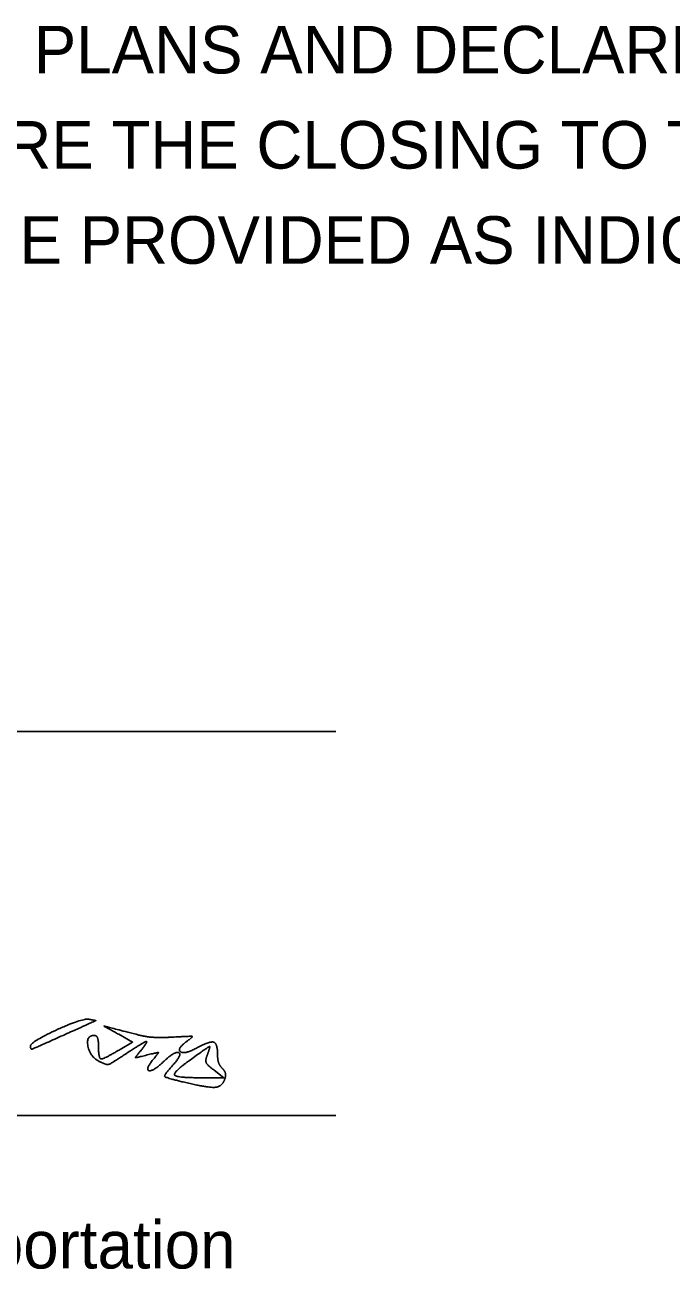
# Model space of a CAD drawing. Extents: x 0 to 34, y 0 to 22.
# Drawn here: x 27.114 to 29.016, y 7.177 to 10.877 of the extents above; entities that cross this region are included whole.
import ezdxf

# ---------------------------------------------------------------- set-up
doc = ezdxf.new("R2010")
doc.units = 0
doc.layers.add('SH_Data', color=7, linetype='Continuous')
doc.layers.add('SH_Text', color=7, linetype='Continuous')

msp = doc.modelspace()

# ---------------------------------------------------------------- linework, layer by layer
at = {"layer": 'SH_Data'}
for p, q in [((24.5279, 8.7985), (28.0279, 8.7985)), ((24.5279, 7.6691), (28.0279, 7.6691))]:
    msp.add_line(p, q, dxfattribs=at)
at = {"layer": 'SH_Text'}
for p, q in [((27.1295, 7.8733), (27.1295, 7.8733)), ((27.582, 7.767), (27.582, 7.767))]:
    msp.add_line(p, q, dxfattribs=at)
for points in [[(27.3933, 7.8637), (27.4297, 7.8852), (27.3889, 7.9081)], [(27.642, 7.7802), (27.6982, 7.7802), (27.6695, 7.8024)]]:
    msp.add_lwpolyline(points, dxfattribs=at)
for points in [[(27.1295, 7.8733), (27.1295, 7.8857), (27.2823, 7.956), (27.3012, 7.9523)], [(27.3012, 7.9523), (27.3219, 7.9482), (27.3226, 7.9487), (27.201, 7.894)], [(27.3889, 7.9081), (27.3461, 7.9323), (27.3452, 7.9323), (27.4482, 7.9059)], [(27.201, 7.894), (27.1385, 7.8659), (27.1295, 7.8633), (27.1295, 7.8733)], [(27.3305, 7.8291), (27.304, 7.8433), (27.293, 7.9047), (27.317, 7.9047)], [(27.317, 7.9047), (27.3238, 7.9047), (27.3295, 7.8906), (27.3295, 7.8734)], [(27.4529, 7.8589), (27.4773, 7.8885), (27.4615, 7.8847), (27.4052, 7.8475)], [(27.4482, 7.9059), (27.4688, 7.9006), (27.5138, 7.8979), (27.5482, 7.8998)], [(27.5482, 7.8998), (27.6031, 7.9029), (27.608, 7.9012), (27.5881, 7.8864)], [(27.5881, 7.8864), (27.5593, 7.865), (27.5822, 7.8486), (27.6159, 7.8666)], [(27.6159, 7.8666), (27.6561, 7.8881), (27.6795, 7.8824), (27.6795, 7.8509)], [(27.3295, 7.8734), (27.3295, 7.8366), (27.3438, 7.8344), (27.3933, 7.8637)], [(27.4052, 7.8475), (27.3652, 7.8209), (27.3519, 7.8177), (27.3305, 7.8291)], [(27.4723, 7.8472), (27.4392, 7.8389), (27.4374, 7.84), (27.4529, 7.8589)], [(27.4924, 7.8364), (27.507, 7.854), (27.5047, 7.8552), (27.4723, 7.8472)], [(27.5462, 7.815), (27.5767, 7.8487), (27.5551, 7.8596), (27.5211, 7.8277)], [(27.6497, 7.8479), (27.6596, 7.8737), (27.6514, 7.8706), (27.5888, 7.825)], [(27.6695, 7.8024), (27.6491, 7.818), (27.6434, 7.8313), (27.6497, 7.8479)], [(27.6795, 7.8509), (27.6795, 7.8351), (27.6858, 7.8158), (27.6936, 7.808)], [(27.5211, 7.8277), (27.4892, 7.7977), (27.4661, 7.8047), (27.4924, 7.8364)], [(27.582, 7.767), (27.5272, 7.78), (27.5215, 7.7877), (27.5462, 7.815)], [(27.5888, 7.825), (27.5461, 7.7939), (27.5626, 7.78), (27.642, 7.7802)], [(27.6936, 7.808), (27.7014, 7.8002), (27.7044, 7.7851), (27.7003, 7.7743)], [(27.7003, 7.7743), (27.6922, 7.7532), (27.651, 7.7507), (27.582, 7.767)]]:
    msp.add_open_spline(points, degree=2, dxfattribs=at)

# ---------------------------------------------------------------- texts
at = {"layer": 'SH_Data'}
for s, p in [(' I HEREBY APPROVE THESE PLANS AND DECLARE THAT THE MAKING OF THIS', (24.5279, 10.735)), ('IMPROVEMENT WILL REQUIRE THE CLOSING TO TRAFFIC OF THE HIGHWAY', (24.5279, 10.455)), ('AND THAT DETOURS WILL BE PROVIDED AS INDICATED ON SHEETS ', (24.5279, 10.175))]:
    msp.add_text(s, height=0.14, dxfattribs=at).set_placement(p)
at = {"layer": 'SH_Text'}
msp.add_text('Director, Department of Transportation', height=0.14, dxfattribs=at).set_placement((24.5279, 7.2191))

doc.saveas('drawing.dxf')
